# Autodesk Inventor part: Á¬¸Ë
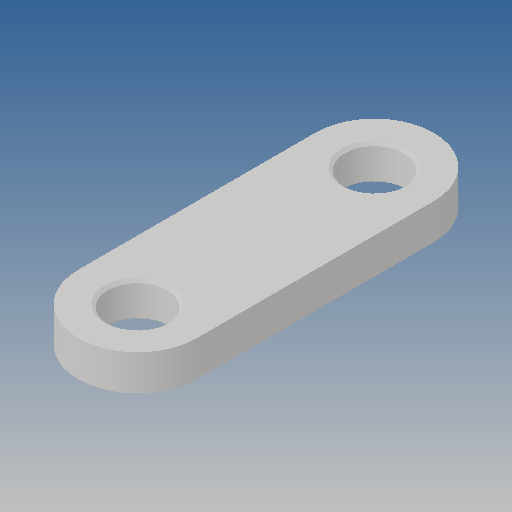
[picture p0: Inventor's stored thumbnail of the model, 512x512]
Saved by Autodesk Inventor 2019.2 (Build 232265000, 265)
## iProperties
Created: 2013-07
Part Number: Á¬¸Ë
Material: Ogólny
Document SubType Name: Modeling
Designer: CADENGINEERING4
Density: 1 g/cm^3
Appearance: Domyślna
Author: CADENGINEERING4
Revision Number: ÈÎºÎ
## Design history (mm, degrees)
feature "CALC80-Á¬¸Ë.bak-1-solid1"
node "Bryła1"
